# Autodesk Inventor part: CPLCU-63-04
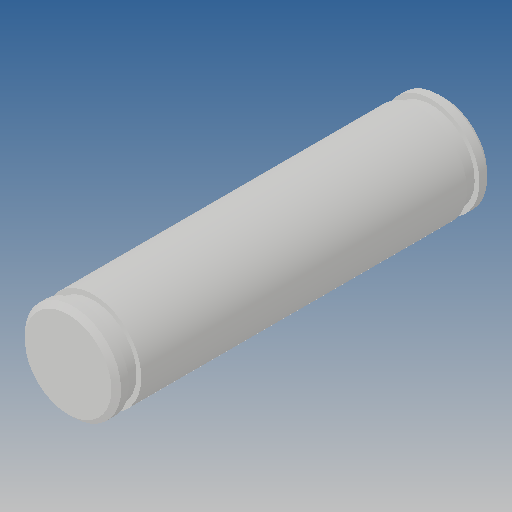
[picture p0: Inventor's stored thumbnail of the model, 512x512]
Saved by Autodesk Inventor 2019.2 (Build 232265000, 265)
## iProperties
Created: 2010-03
Part Number: CPLCU-63-04
Material: Ogólny
Document SubType Name: Modeling
Designer: CADENGINEERING4
Density: 1 g/cm^3
Appearance: Domyślna
Author: CADENGINEERING4
Revision Number: 2LAST_VERSION
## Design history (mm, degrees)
feature "Baza1"
node "Bryła1"
